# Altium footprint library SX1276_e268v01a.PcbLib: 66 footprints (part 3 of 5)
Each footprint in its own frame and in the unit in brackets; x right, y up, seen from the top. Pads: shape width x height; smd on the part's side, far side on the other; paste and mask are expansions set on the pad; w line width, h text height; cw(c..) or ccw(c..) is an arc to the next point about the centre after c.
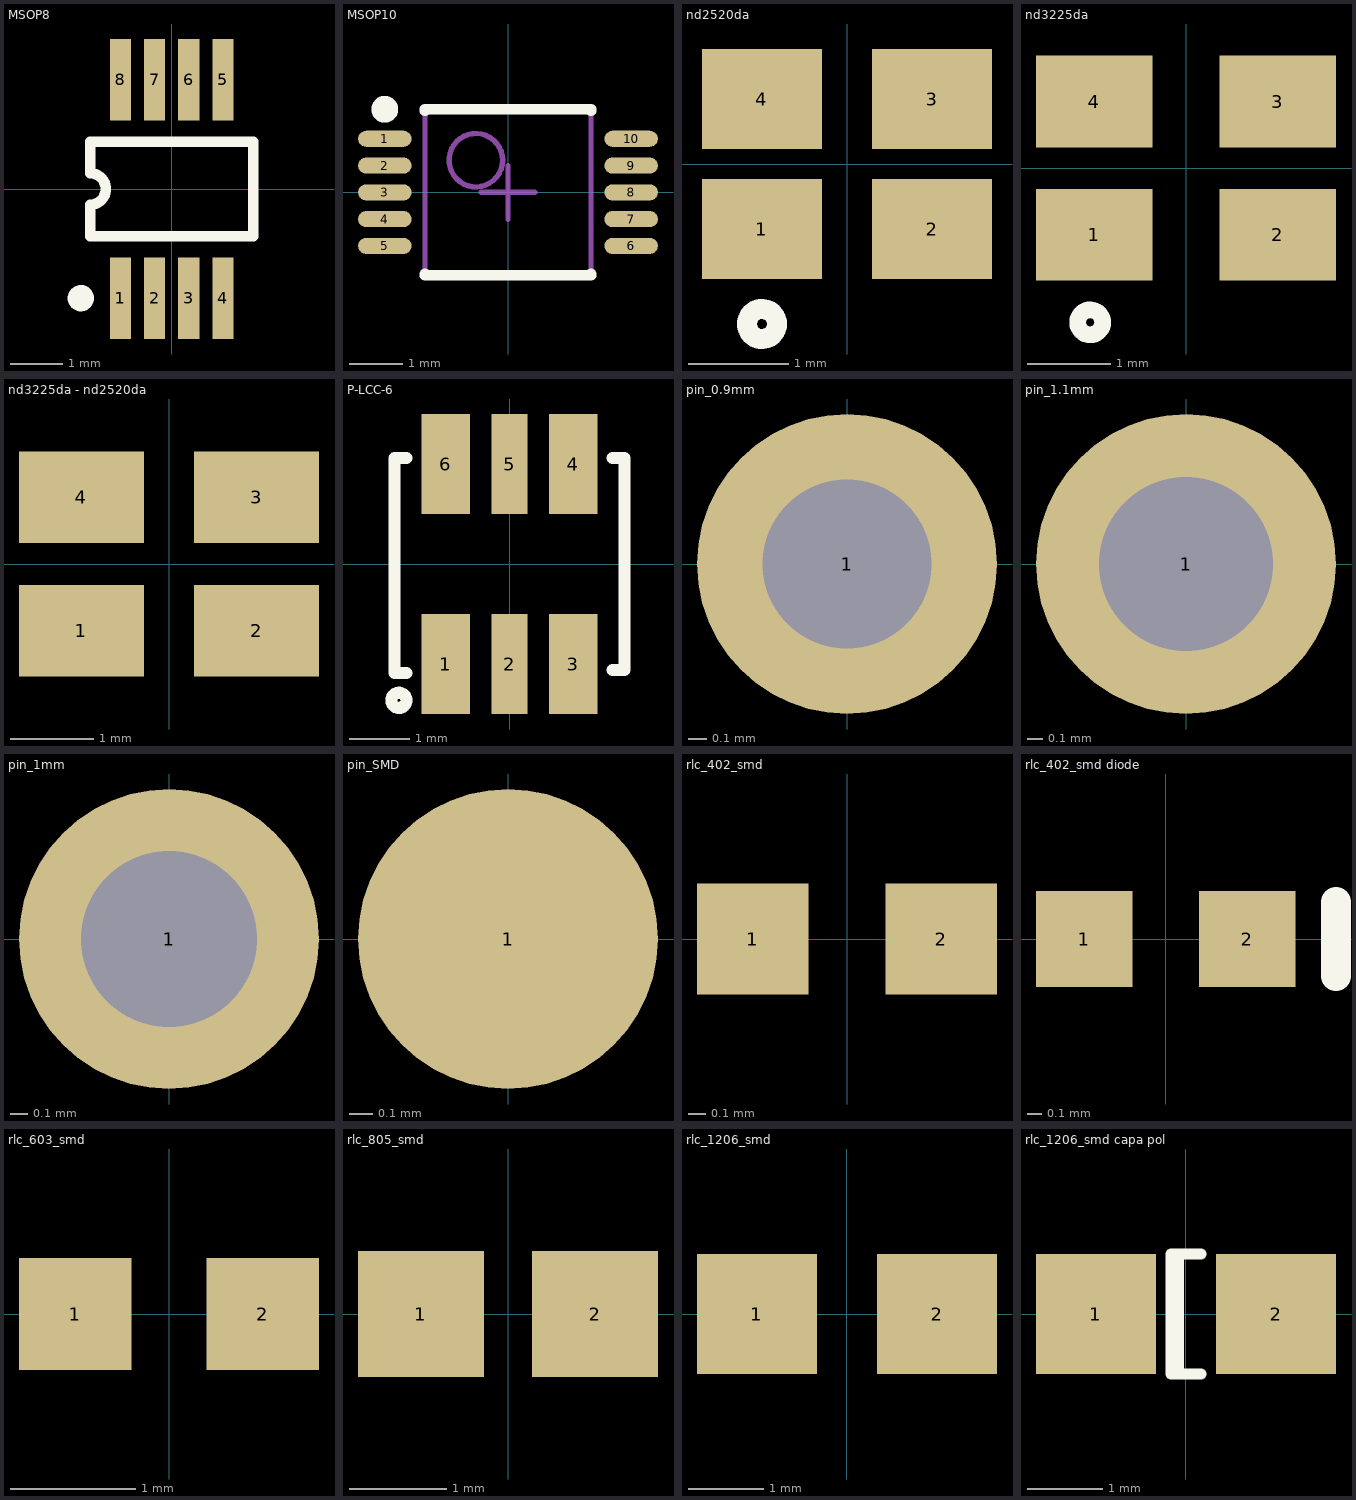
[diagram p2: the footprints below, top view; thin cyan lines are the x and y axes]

## MSOP8 [mm] "Shrink Small Outline; 8 Leads; Body Width 3 mm; Pitch 0.65 mm"
height 1.17
pads (8):
  rect 0.4x1.55 smd: 1(-0.975,-2.075) 2(-0.325,-2.075) 3(0.325,-2.075) 4(0.975,-2.075) 5(0.975,2.075) 6(0.325,2.075) 7(-0.325,2.075) 8(-0.975,2.075)
Top Overlay:
  circle w0.25: c-1.725,-2.075 r0.125
  lines w0.2: -1.55,-0.9 -1.55,-0.3 ccw(c-1.55,0) -1.55,0.3 -1.55,0.9 1.55,0.9 1.55,-0.9 -1.55,-0.9

## MSOP10 [mm] "MSPO, 10-Leads, Body 3x3 mm, Pitch 0.5mm, IPC Medium Density"
height 0.8
pads (10):
  oval 1x0.3 smd: 1(-2.3,1) 2(-2.3,0.5) 3(-2.3,0) 4(-2.3,-0.5) 5(-2.3,-1) 6(2.3,-1) 7(2.3,-0.5) 8(2.3,0) 9(2.3,0.5) 10(2.3,1)
Top Overlay:
  circle w0.25: c-2.3,1.55 r0.125
  lines w0.2: -1.55,-1.525 -1.55,-1.55 1.55,-1.55 1.55,-1.525 ; -1.55,1.525 -1.55,1.55 1.55,1.55 1.55,1.525
Mechanical 13:
  circle w0.1: c-0.6,0.6 r0.5
  lines w0.1: -1.55,-1.55 -1.55,1.55 1.55,1.55 1.55,-1.55 -1.55,-1.55
Mechanical 15:
  lines w0.1: -0.5,0 0.5,0 ; 0,-0.5 0,0.5
3D body: height 0.8, standoff 0, extent -1.55,-1.55 1.55,1.55

## nd2520da [mm] "Crystal SMD 2.5x2.0mm"
height 0.7
pads (4):
  rect 1.2x1 smd mask+0.05: 1(-0.85,-0.65) 2(0.85,-0.65) 3(0.85,0.65) 4(-0.85,0.65)
Top Overlay:
  circle w0.2: c-0.85,-1.6 r0.15
3D body: height 1, standoff 0, extent -1.25,-1 1.25,1

## nd3225da [mm] "Crystal SMD 3.2x2.5mm"
height 0.8
pads (4):
  rect 1.4x1.1 smd mask+0.05: 1(-1.1,-0.8) 2(1.1,-0.8) 3(1.1,0.8) 4(-1.1,0.8)
Top Overlay:
  circle w0.2: c-1.15,-1.85 r0.15
3D body: height 1, standoff 0, extent -1.6,-1.25 1.6,1.25

## nd3225da - nd2520da [mm] "Crystal SMD 3.2x2.5mm compatible with 2.5x2.0mm"
height 0.8
pads (4):
  rect 1.5x1.1 smd mask+0.05: 1(-1.05,-0.8) 2(1.05,-0.8) 3(1.05,0.8) 4(-1.05,0.8)
3D body: height 1, standoff 0, extent -1.6,-1.25 1.6,1.25

## P-LCC-6 [mm] "P-LCC-6 Package"
height 1.25
pads (6):
  rect 0.8x1.65 smd: 1(-1.05,-1.65) 3(1.05,-1.65) 4(1.05,1.65) 6(-1.05,1.65)
  rect 0.6x1.65 smd: 2(0,-1.65) 5(0,1.65)
Top Overlay:
  circle w0.2: c-1.825,-2.25 r0.125
  lines w0.2: -1.7,-1.8 -1.9,-1.8 -1.9,1.75 -1.7,1.75 ; 1.7,-1.75 1.9,-1.75 1.9,1.75 1.7,1.75

## pin_0.9mm [mm] "Generic Pin 0.9mm; 1 Lead"
height 1
pads (1):
  round 1.6 hole 0.9 mask+0.05: 1(0,0)

## pin_1.1mm [mm] "Generic Pin 1.1mm; 1 Lead"
height 1
pads (1):
  round 1.9 hole 1.1 mask+0.05: 1(0,0)

## pin_1mm [mm] "Generic Pin 1.1mm; 1 Lead"
height 1
pads (1):
  round 1.7 hole 1 paste+0 mask+0.05: 1(0,0)

## pin_SMD [mm] "Generic Pin; 1 pin SMD"
height 0.5
pads (1):
  round 1.27 smd paste-1 mask+0.05: 1(0,0)

## rlc_402_smd [mm] "Chip SMD component 402; Body 1.0 x 0.5 mm (LxW typ)"
height 0.8
pads (2):
  rect 0.65x0.65 smd mask+0.05: 1(-0.55,0) 2(0.55,0)

## rlc_402_smd diode [mm] "Chip SMD component 402; Body 1.0 x 0.5 mm (LxW typ)"
height 0.8
pads (2):
  rect 0.65x0.65 smd mask+0.05: 1(-0.55,0) 2(0.55,0)
Top Overlay:
  lines w0.2: 1.15,-0.25 1.15,0.25

## rlc_603_smd [mm] "Chip SMD component 603; Body 1.6 x 0.8mm (LxW typ)"
height 1
pads (2):
  rect 0.9x0.9 smd paste+0 mask+0.05: 1(-0.75,0) 2(0.75,0)

## rlc_805_smd [mm] "Chip SMD component 805; Body 2.0 x 1.25 mm (LxW typ)"
height 1.4
pads (2):
  rect 1.3x1.3 smd mask+0.05: 1(-0.9,0) 2(0.9,0)

## rlc_1206_smd [mm] "Chip SMD component 1206; Body 3.2 x 1.6 mm (LxW typ)"
height 2
pads (2):
  rect 1.6x1.6 smd mask+0.05: 1(-1.2,0) 2(1.2,0)

## rlc_1206_smd capa pol [mm] "Chip SMD component 1206; Body 3.2 x 1.6 mm (LxW typ)"
height 2
pads (2):
  rect 1.6x1.6 smd mask+0.05: 1(-1.2,0) 2(1.2,0)
Top Overlay:
  lines w0.15: -0.1,-0.8 -0.1,0.8 ; 0.2,-0.8 -0.2,-0.8 -0.2,0.8 0.2,0.8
